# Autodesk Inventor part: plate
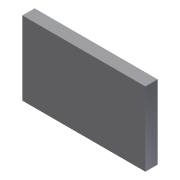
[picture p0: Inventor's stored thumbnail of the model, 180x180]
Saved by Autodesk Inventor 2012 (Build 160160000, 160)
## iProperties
Created: 2010-05
Part Number: plate
Document SubType Name: Modeling
Designer: CADSoft
Density: 1 g/cm^3
Material: Default
Author: CADSoft
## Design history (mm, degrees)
sketch "Sketch1"
  geometry: L1 (101.431, -46.382)-(51.431, -46.382); L2 (51.431, -46.382)-(51.431, -76.382); L3 (51.431, -76.382)-(101.431, -76.382); L4 (101.431, -76.382)-(101.431, -46.382); 1 further point
  constraints: 8 end point, 2 parallel, 1 horizontal, 1 perpendicular
  dimensions: "d0" = 30 distance of L3.end L1.start; "d1" = 50 distance of L1.start L1.end
extrude "Extrusion1" new body sketch "Sketch1" distance "d2" = 5; taper "d3" = 0 deg
body "Solid1"
